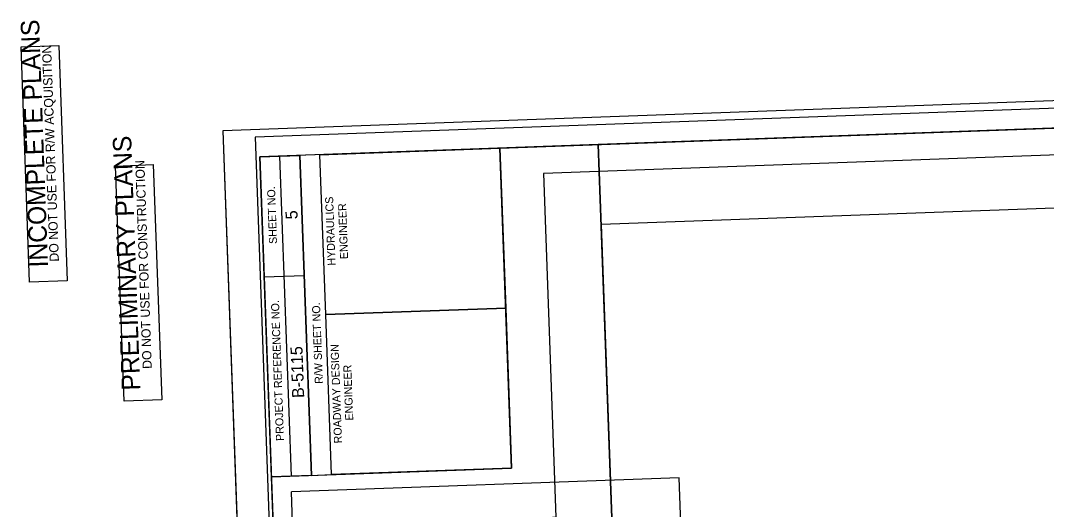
# Model space of a CAD drawing. Extents: x 2065256 to 2066537, y 145527 to 147314.
# Drawn here: x 2065256 to 2065896, y 147008 to 147314 of the extents above; entities that cross this region are included whole.
import ezdxf

# ---------------------------------------------------------------- set-up
doc = ezdxf.new("R2010")
doc.units = 0
for name, color, linetype in [('Prop Dimension', 7, 'Continuous'), ('Sheet Clip Boundary CELL', 7, 'Continuous'), ('Sheet Cutting Line CELL', 7, 'Continuous'), ('Sheet Data Field CELL', 7, 'Continuous'), ('Sheet Layout Plan Border', 7, 'Continuous'), ('Sheet Plan CELL', 7, 'Continuous'), ('Sheet Plan Layout CELL', 7, 'Continuous'), ('Sheet Plot Border Inside CELL', 7, 'Continuous'), ('Sheet Plot Border Outside CELL', 7, 'Continuous'), ('Sheet Sticker Incomplete CELL', 7, 'Continuous'), ('Sheet Sticker Preliminary CELL', 7, 'Continuous')]:
    doc.layers.add(name, color=color, linetype=linetype)

msp = doc.modelspace()

# ---------------------------------------------------------------- linework, layer by layer
at = {"layer": 'Prop Dimension'}
for p, q in [((2065666.92, 147028.09), (2065424.78, 147019.34)), ((2065683.84, 146559.92), (2065666.92, 147028.09)), ((2065441.7, 146551.17), (2065424.78, 147019.34))]:
    msp.add_line(p, q, dxfattribs=at)
at = {"layer": 'Sheet Clip Boundary CELL'}
msp.add_lwpolyline([(2066225.3, 145855.32), (2066356.28, 145860.05), (2066306.24, 147244.42), (2065582.18, 147218.25), (2065589.94, 147003.52), (2065566.99, 147001.07), (2065609.27, 145831.43)], close=True, dxfattribs=at)
at = {"layer": 'Sheet Cutting Line CELL'}
msp.add_line((2065381.93, 147244.73), (2065442.74, 145562.33), dxfattribs=at)
at = {"layer": 'Sheet Layout Plan Border'}
msp.add_lwpolyline([(2066506.71, 145817.42), (2066456.14, 147216.52), (2065618.17, 147186.22), (2065625.01, 146997.09), (2065413.66, 146989.45), (2065457.4, 145779.49)], close=True, dxfattribs=at)
at = {"layer": 'Sheet Plan CELL'}
for p, q in [((2065424.77, 147029.07), (2065417.56, 147228.99)), ((2065437.3, 147029.54), (2065430.05, 147229.44)), ((2065437.3, 147029.54), (2065430.05, 147229.44)), ((2065407.79, 147153.57), (2065432.77, 147154.52)), ((2065446.17, 147129.97), (2065558.55, 147134.05)), ((2065437.3, 147029.54), (2065449.78, 147029.99))]:
    msp.add_line(p, q, dxfattribs=at)
for points in [[(2065405.01, 147228.58), (2065459.2, 145729.52), (2066508.52, 145767.45), (2066454.33, 147266.48)], [(2066508.52, 145767.45), (2065459.23, 145729.49), (2065412.23, 147028.63), (2065562.19, 147034.07), (2065554.98, 147233.97), (2066454.33, 147266.48)], [(2065446.17, 147129.97), (2065442.54, 147229.9), (2065554.98, 147233.97), (2065558.61, 147134.04)], [(2065412.23, 147028.63), (2065405.01, 147228.58), (2065430.05, 147229.44), (2065437.3, 147029.54)], [(2065449.78, 147029.99), (2065446.17, 147129.97), (2065558.61, 147134.04), (2065562.19, 147034.07)]]:
    msp.add_lwpolyline(points, close=True, dxfattribs=at)
at = {"layer": 'Sheet Plan Layout CELL'}
for points in [[(2065459.23, 145729.49), (2066508.52, 145767.45), (2066454.33, 147266.47), (2065616.37, 147236.18), (2065625.01, 146997.09), (2065413.66, 146989.45)], [(2065625.01, 146997.09), (2065616.36, 147236.2), (2065405.01, 147228.59), (2065413.66, 146989.45)]]:
    msp.add_lwpolyline(points, close=True, dxfattribs=at)
at = {"layer": 'Sheet Plot Border Inside CELL'}
msp.add_lwpolyline([(2066516.57, 145614.15), (2066456.38, 147279.05), (2065402.08, 147240.95), (2065462.26, 145576.04)], close=True, dxfattribs=at)
at = {"layer": 'Sheet Plot Border Outside CELL'}
msp.add_lwpolyline([(2066537.03, 145601.88), (2066476.21, 147284.29), (2065381.93, 147244.73), (2065442.74, 145562.33)], close=True, dxfattribs=at)
at = {"layer": 'Sheet Sticker Incomplete CELL'}
msp.add_lwpolyline([(2065284.76, 147151.14), (2065261.27, 147150.29), (2065255.96, 147297.19), (2065279.45, 147298.04)], close=True, dxfattribs=at)
at = {"layer": 'Sheet Sticker Preliminary CELL'}
msp.add_lwpolyline([(2065343.77, 147076.77), (2065320.29, 147075.92), (2065314.97, 147222.82), (2065338.46, 147223.67)], close=True, dxfattribs=at)

# ---------------------------------------------------------------- texts
at = {"layer": 'Sheet Data Field CELL'}
for s, p in [('5', (2065428.69, 147189.65)), ('B-5115', (2065432.78, 147078.01))]:
    msp.add_text(s, height=7.5, rotation=92.07025, dxfattribs=at).set_placement(p)
at = {"layer": 'Sheet Plan CELL'}
for s, height, p in [('SHEET NO.', 5, (2065415.81, 147174.22)), ('HYDRAULICS', 5, (2065452.34, 147160.68)), ('ENGINEER', 5, (2065460.16, 147164.73)), ('PROJECT REFERENCE NO.', 5.0001, (2065420.15, 147051.13)), ('R/W SHEET NO.', 5.0001, (2065444.42, 147086.83)), ('ROADWAY DESIGN', 5.0001, (2065456.38, 147049.62)), ('ENGINEER', 5, (2065463.4, 147063.87))]:
    msp.add_text(s, height=height, rotation=92.07025, dxfattribs=at).set_placement(p)
at = {"layer": 'Sheet Sticker Incomplete CELL'}
for s, height, p in [('INCOMPLETE PLANS', 11.52, (2065272.74, 147159.66)), ('DO NOT USE FOR R/W ACQUISITION', 5.76, (2065279.57, 147163.16))]:
    msp.add_text(s, height=height, rotation=92.07024, dxfattribs=at).set_placement(p)
at = {"layer": 'Sheet Sticker Preliminary CELL'}
for s, height, p in [('PRELIMINARY PLANS', 11.52, (2065330.39, 147082.79)), ('DO NOT USE FOR CONSTRUCTION', 5.76, (2065337.62, 147096.16))]:
    msp.add_text(s, height=height, rotation=92.07024, dxfattribs=at).set_placement(p)

doc.saveas('drawing.dxf')
